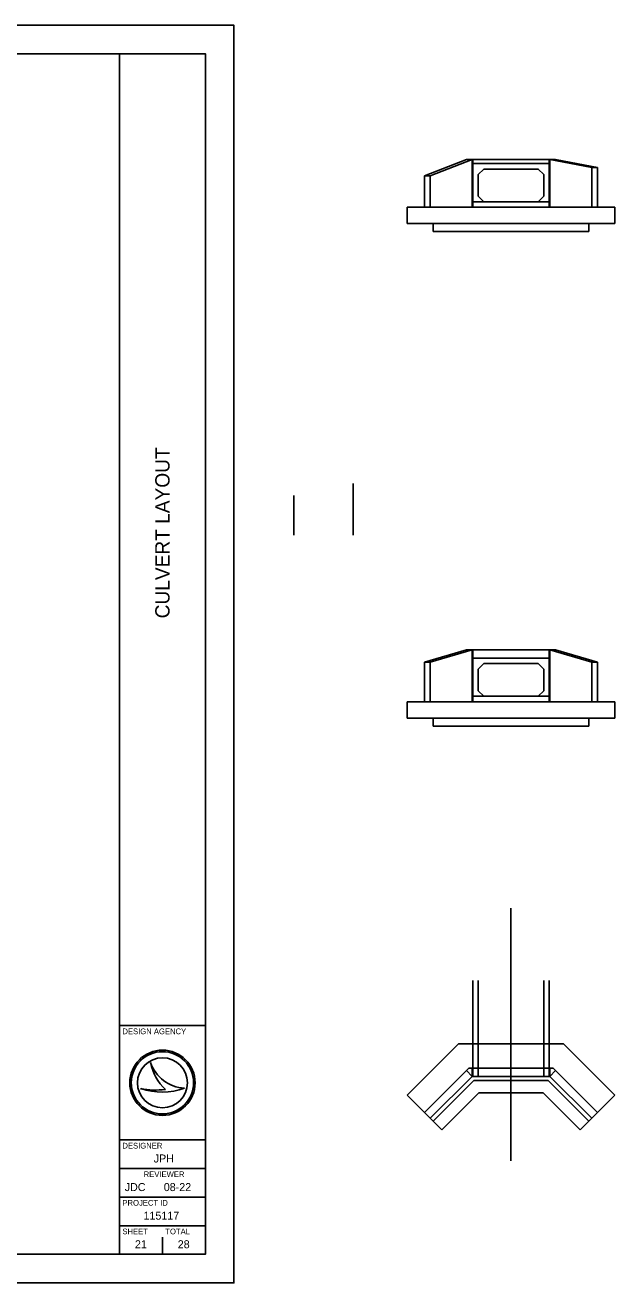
# Model space of a CAD drawing. Extents: x 350 to 634, y 6 to 160.
# Drawn here: x 562.3 to 634.5, y 6.4 to 160.4 of the extents above; entities that cross this region are included whole.
import ezdxf

# ---------------------------------------------------------------- set-up
doc = ezdxf.new("R2010")
doc.units = 0
for name, color, linetype in [('DR_P_Culvert', 7, 'Continuous'), ('GE_P_Alignment', 7, 'Continuous'), ('SH_Border', 7, 'Continuous'), ('SH_Cut_Line', 7, 'Continuous'), ('SH_Data', 7, 'Continuous'), ('TX_P_5', 7, 'Continuous')]:
    doc.layers.add(name, color=color, linetype=linetype)

msp = doc.modelspace()

# ---------------------------------------------------------------- linework, layer by layer
at = {"layer": 'DR_P_Culvert'}
for p, q in [((611.17, 142), (616.29, 144)), ((611.87, 142), (617, 144)), ((617, 144), (616.29, 144)), ((617, 144), (617, 138.16)), ((617, 144), (617.08, 144)), ((617.08, 144), (617.08, 138.16)), ((617.08, 144), (626.42, 144)), ((617.08, 143.5), (626.42, 143.5)), ((626.42, 144), (626.42, 138.16)), ((626.42, 144), (626.5, 144)), ((626.5, 144), (626.5, 138.16)), ((631.63, 143), (626.5, 144)), ((626.5, 144), (627.21, 144)), ((627.21, 144), (632.33, 143)), ((611.17, 138.16), (611.17, 142)), ((611.87, 142), (611.17, 142)), ((611.87, 138.16), (611.87, 142)), ((631.63, 138.16), (631.63, 143)), ((631.63, 143), (632.33, 143)), ((632.33, 138.16), (632.33, 143)), ((618.42, 138.83), (617.08, 138.83)), ((625.08, 138.83), (626.42, 138.83)), ((609.05, 138.16), (634.46, 138.16)), ((609.05, 136.16), (609.05, 138.16)), ((634.46, 136.16), (634.46, 138.16)), ((609.05, 136.16), (634.46, 136.16)), ((612.23, 135.16), (612.23, 136.16)), ((631.27, 135.16), (631.27, 136.16)), ((612.23, 135.16), (631.27, 135.16)), ((616.29, 83.94), (611.17, 82.44)), ((611.87, 82.44), (617, 83.94)), ((617, 83.94), (616.29, 83.94)), ((617, 83.94), (617, 77.6)), ((617, 83.94), (617.08, 83.94)), ((617.08, 83.94), (617.08, 77.6)), ((617.08, 83.94), (626.42, 83.94)), ((626.42, 83.94), (626.42, 77.6)), ((626.42, 83.94), (626.5, 83.94)), ((626.5, 83.94), (626.5, 77.6)), ((631.63, 82.44), (626.5, 83.94)), ((626.5, 83.94), (627.21, 83.94)), ((627.21, 83.94), (632.33, 82.44)), ((611.17, 77.6), (611.17, 82.44)), ((611.87, 82.44), (611.17, 82.44)), ((611.87, 77.6), (611.87, 82.44)), ((617.08, 82.94), (626.42, 82.94)), ((631.63, 77.6), (631.63, 82.44)), ((632.33, 82.44), (631.63, 82.44)), ((632.33, 77.6), (632.33, 82.44)), ((609.05, 77.6), (634.46, 77.6)), ((609.05, 75.6), (609.05, 77.6)), ((618.42, 78.27), (617.08, 78.27)), ((625.08, 78.27), (626.42, 78.27)), ((634.46, 75.6), (634.46, 77.6)), ((609.05, 75.6), (634.46, 75.6)), ((612.23, 74.6), (612.23, 75.6)), ((631.27, 74.6), (631.27, 75.6)), ((612.23, 74.6), (631.27, 74.6)), ((617.08, 43.47), (617.08, 31.72)), ((617.75, 43.47), (617.75, 31.72)), ((625.75, 43.47), (625.75, 31.72)), ((626.42, 43.47), (626.42, 31.72)), ((609.05, 29.42), (615.34, 35.72)), ((615.34, 35.72), (628.16, 35.72)), ((634.46, 29.42), (628.16, 35.72)), ((611.17, 27.3), (616.59, 32.72)), ((616.29, 32.43), (617, 31.72)), ((616.59, 32.72), (626.92, 32.72)), ((617, 31.72), (617, 32.72)), ((626.5, 31.72), (626.5, 32.72)), ((627.21, 32.43), (626.5, 31.72)), ((632.33, 27.3), (626.92, 32.72)), ((611.87, 26.6), (617, 31.72)), ((612.23, 26.24), (617.21, 31.22)), ((617, 31.72), (617.08, 31.72)), ((626.42, 31.72), (617.08, 31.72)), ((617.21, 31.22), (626.29, 31.22)), ((631.27, 26.24), (626.29, 31.22)), ((626.42, 31.72), (626.5, 31.72)), ((631.63, 26.6), (626.5, 31.72)), ((609.05, 29.42), (613.29, 25.18)), ((613.29, 25.18), (617.83, 29.72)), ((617.83, 29.72), (625.67, 29.72)), ((630.21, 25.18), (625.67, 29.72)), ((634.46, 29.42), (630.21, 25.18))]:
    msp.add_line(p, q, dxfattribs=at)
for points in [[(618.42, 142.83), (617.75, 142.16), (617.75, 139.5), (618.42, 138.83), (625.08, 138.83), (625.75, 139.5), (625.75, 142.16), (625.08, 142.83)], [(618.42, 82.27), (617.75, 81.6), (617.75, 78.94), (618.42, 78.27), (625.08, 78.27), (625.75, 78.94), (625.75, 81.6), (625.08, 82.27)], [(617.08, 32.72), (617.08, 31.72), (617, 31.72), (617, 32.72)], [(626.5, 32.72), (626.5, 31.72), (626.42, 31.72), (626.42, 32.72)]]:
    msp.add_lwpolyline(points, close=True, dxfattribs=at)
at = {"layer": 'GE_P_Alignment'}
msp.add_line((621.75, 52.32), (621.75, 21.4), dxfattribs=at)
at = {"layer": 'SH_Border'}
for p, q in [((573.86, 9.94), (573.86, 156.94)), ((573.86, 37.94), (584.36, 37.94)), ((573.86, 23.94), (584.36, 23.94)), ((573.86, 20.44), (584.36, 20.44)), ((573.86, 16.94), (584.36, 16.94)), ((573.86, 13.44), (584.36, 13.44))]:
    msp.add_line(p, q, dxfattribs=at)
msp.add_lwpolyline([(360.36, 156.94), (584.36, 156.94), (584.36, 9.94), (360.36, 9.94)], close=True, dxfattribs=at)
at = {"layer": 'SH_Cut_Line'}
msp.add_lwpolyline([(349.86, 6.44), (587.86, 6.44), (587.86, 160.44), (349.86, 160.44)], close=True, dxfattribs=at)
at = {"layer": 'SH_Data'}
for p, q in [((577.64, 33.42), (577.64, 33.42)), ((579.11, 30.94), (579.11, 30.94)), ((576.44, 30.22), (576.44, 30.22)), ((581.8, 30.29), (581.8, 30.29)), ((576.48, 11.17), (576.48, 11.17)), ((579.11, 9.94), (579.11, 12.04))]:
    msp.add_line(p, q, dxfattribs=at)
for radius in [4, 3.81, 3.81, 3.06]:
    msp.add_circle((579.11, 30.94), radius, dxfattribs=at)
for centre, radius, start, end in [((582.03, 34.92), 4.64, 198.9257, 198.9319), ((583.88, 34.7), 6.36, 191.6379, 191.6421), ((582.03, 34.92), 4.64, 198.9319, 267.1657), ((583.88, 34.7), 6.36, 191.6421, 226.0947), ((579.02, 37.9), 8.1, 251.4576, 290.0832), ((578.29, 40.18), 10.13, 259.4964, 259.4995), ((579.02, 37.9), 8.1, 251.4527, 251.4576), ((578.29, 40.18), 10.13, 259.4995, 276.6672)]:
    msp.add_arc(centre, radius, start, end, dxfattribs=at)
at = {"layer": 'TX_P_5'}
for p, q in [((602.43, 98.01), (602.43, 104.34)), ((595.18, 98.01), (595.18, 102.84))]:
    msp.add_line(p, q, dxfattribs=at)

# ---------------------------------------------------------------- texts
at = {"layer": 'SH_Data'}
msp.add_text('CULVERT LAYOUT', height=1.75, rotation=90, dxfattribs=at).set_placement((579.98, 87.81))
for s, height, p in [('DESIGN AGENCY', 0.7, (574.21, 36.89)), ('DESIGNER', 0.7, (574.21, 22.89)), ('JPH', 0.98, (578.04, 21.18)), ('REVIEWER', 0.7, (576.81, 19.39)), ('JDC', 0.98, (574.49, 17.68)), ('08-22', 0.98, (579.27, 17.68)), ('PROJECT ID', 0.7, (574.21, 15.89)), ('115117', 0.98, (576.79, 14.18)), ('SHEET', 0.7, (574.21, 12.39)), ('TOTAL', 0.7, (579.46, 12.39)), ('21', 0.98, (575.74, 10.68)), ('28', 0.98, (580.98, 10.68))]:
    msp.add_text(s, height=height, dxfattribs=at).set_placement(p)

doc.saveas('drawing.dxf')
